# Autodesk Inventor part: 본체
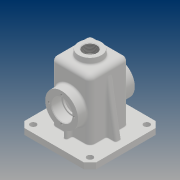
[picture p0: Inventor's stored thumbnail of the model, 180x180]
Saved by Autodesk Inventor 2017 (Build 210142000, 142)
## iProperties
Part Number: 본체
Material: 일반
Document SubType Name: Modeling
Designer: 20
Density: 1 g/cm^3
Appearance: 기본값
Mass: 292.115 g
Surface Area: 897.365 cm^2
Volume: 292.115 cm^3
Author: 20
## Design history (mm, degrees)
sketch "스케치1"
  geometry: L1 (-32.5, -32.5)-(32.5, -32.5); L2 (32.5, -32.5)-(32.5, 32.5); L3 (32.5, 32.5)-(-32.5, 32.5); L4 (-32.5, 32.5)-(-32.5, -32.5); L5 (-32.5, -32.5)-(32.5, 32.5); L6 (32.5, -32.5)-(-32.5, 32.5); 1 further point
  constraints: 12 end point, 2 midpoint, 2 parallel, 1 horizontal, 1 perpendicular
  dimensions: "d0" = 65 distance of L1.end L2.end; "d1" = 65 distance of L1.start L1.end
extrude "돌출1" new body sketch "스케치1" distance "d2" = 100; taper "d3" = 0 deg
feature "쉘1" dims "d4" = 5
sketch "스케치2"
  geometry: L1 (5, 0)-(60, 0) reference; C1 r 27.5 at (32.5, 45); 2 further points
  constraints: 1 centre point, 1 midpoint, 1 vertical alignment
  dimensions: "d5" = 55 diameter of C1; "d6" = 45 distance of point (32.5, 0) C1.centre
extrude "돌출2" join sketch "스케치2" distance "d7" = 15; taper "d8" = 0 deg
sketch "스케치3"
  geometry: C1 r 17.5 at (0, 0); C2 r 27.5 at (0, 0) reference; 1 further point
  constraints: 1 centre point, 1 concentric
  dimensions: "d9" = 35 diameter of C1
extrude "돌출3" cut sketch "스케치3" distance "d10" = 17; taper "d11" = 0 deg
sketch "스케치4"
  geometry: C1 r 15 at (0, 0); C2 r 17.5 at (0, 0) reference; 1 further point
  constraints: 1 centre point, 1 concentric
  dimensions: "d12" = 30 diameter of C1
extrude "돌출4" cut sketch "스케치4" distance "d13" = 3; taper "d14" = 0 deg
sketch "스케치5"
  geometry: C1 r 17.5 at (0, 0) reference; 2 further points
  constraints: 1 vertical alignment
  dimensions: "d15" = 21 distance of C1.centre point (0, 21)
hole "구멍1" sketch "스케치5" at (0, 21) diameter "d16" = 3.242; stored, may be unused: countersink angle "d20" = 90 deg, drill point angle "d22" = 118 deg; dims "d17" = 8, "d18" = 4, "d19" = 2, "d21" = 10
sketch "스케치6"
  geometry: L1 (60, -60)-(-60, -60); L2 (-60, -60)-(-60, 60); L3 (-60, 60)-(60, 60); L4 (60, 60)-(60, -60); L5 (60, -60)-(-60, 60); L6 (-60, -60)-(60, 60); L7 (27.5, -27.5)-(-27.5, -27.5) reference; L8 (-27.5, -27.5)-(-27.5, 27.5) reference; L9 (-27.5, 27.5)-(27.5, 27.5) reference; L10 (27.5, 27.5)-(27.5, -27.5) reference; 1 further point
  constraints: 12 end point, 2 midpoint, 2 parallel, 1 horizontal, 1 perpendicular
  dimensions: "d26" = 120 distance of L2.end L3.end; "d27" = 120 distance of L3.end L1.start
extrude "돌출5" join sketch "스케치6" distance "d28" = 10; taper "d29" = 0 deg
sketch "스케치7"
  geometry: C1 r 5 at (-47.5, -47.5); 1 further point
  constraints: 1 centre point
  dimensions: "d30" = 10 diameter of C1; "d31" = 47.5 horizontal distance of point (0, 0) C1.centre; "d32" = 47.5 horizontal distance of point (0, 0) C1.centre
extrude "돌출6" cut sketch "스케치7" distance "d33" = 10; taper "d34" = 0 deg
sketch "스케치8"
  geometry: C1 r 20 at (0, 0); 1 further point
  constraints: 1 centre point, 1 coincident
  dimensions: "d41" = 40 diameter of C1
extrude "돌출7" join sketch "스케치8" distance "d42" = 10; taper "d43" = -5 deg
hole "구멍2" diameter "d46" = 22.835; stored, may be unused: countersink angle "d50" = 90 deg, drill point angle "d52" = 0 deg; dims "d44" = 10, "d45" = 10, "d47" = 50, "d48" = 4, "d49" = 2, "d51" = 59.3
sketch "스케치9"
  geometry: L1 (48, 0)-(32.5, 87.905); L2 (32.5, 0)-(32.5, 100) reference; L3 (60, 0)-(60, -10) reference; L4 (60, 0)-(-60, 0) reference; 1 further point
  constraints: 2 end point, 2 point on line
  dimensions: "d53" = 12 distance from line of L3 L1.start; "d54" = 100 deg angle of L4 L1
feature "리브1" sketch "스케치9" dims "d55" = 1, "d56" = 10, "d57" = 0, "d58" = 0, "d59" = 1, "d60" = 1
sketch "스케치10"
  geometry: L1 (27.5, 27.5)-(-27.5, 27.5) reference; L2 (3, 27.5)-(3, 42.5); L3 (3, 42.5)-(-3, 42.5); L4 (-3, 42.5)-(-3, 27.5); 1 further point
  constraints: 6 end point, 2 point on line, 2 vertical, 1 horizontal
  dimensions: "d61" = 6 distance between parallel lines of L4 L2; "d62" = 3 distance from line of point (0, 0) L2; "d63" = 15 distance of L3.end L4.end
extrude "돌출8" join sketch "스케치10" stored distance "d64" = 10; taper "d65" = 0 deg
chamfer "모따기1" distance "d66" = 10; stored, may be unused: second distance "d67" = 2, angle "d68" = 45 deg
fillet "모깎기1" dims "d69" = 8
fillet "모깎기2" dims "d70" = 8
fillet "모깎기3" dims "d71" = 3
fillet "모깎기4" dims "d72" = 3
fillet "모깎기5" dims "d73" = 3
fillet "모깎기6" dims "d74" = 1
fillet "모깎기7" dims "d75" = 3
fillet "모깎기8" dims "d76" = 3
fillet "모깎기9" dims "d77" = 3
fillet "모깎기10" dims "d78" = 3
fillet "모깎기11" dims "d79" = 3
chamfer "모따기2" distance "d80" = 1; stored, may be unused: second distance "d81" = 2, angle "d82" = 45 deg
chamfer "모따기3" distance "d83" = 1; stored, may be unused: second distance "d84" = 2, angle "d85" = 45 deg
fillet "모깎기12" dims "d86" = 0.3
node "작업 평면1"
sketch "스케치11"
  geometry: L1 (43.625, -18)-(5.375, -18) reference; L2 (57, 0)-(57, 91) reference; 2 further points
  constraints: 1 other
  dimensions: "d88" = 26 distance from line of L1 point (24.5, 8); "d89" = 32.5 distance from line of point (24.5, 8) L2
feature "엠보싱1" sketch "스케치11" dims "d90" = 0.5, "d91" = 0
node "솔리드1"
pattern_circular "원형 패턴1" dims angle "d24" = 360 deg
mirror "미러1"
pattern_linear "직사각형 패턴1" dims "d37" = 95, "d40" = 95
mirror "미러2"
mirror "미러3"
other parameters: "d87" = 43
